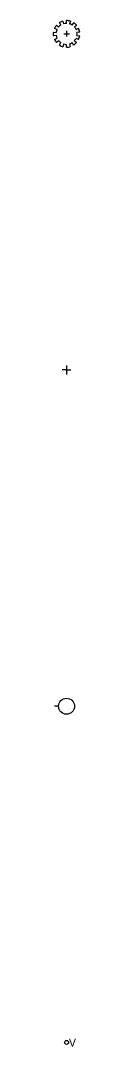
# Model space of a CAD drawing. Extents: x 98 to 2902, y -6 to 903.
# Drawn here: x 898 to 902, y 749.4 to 902 of the extents above; entities that cross this region are included whole.
import ezdxf

# ---------------------------------------------------------------- set-up
doc = ezdxf.new("R2010")
doc.units = 0
for name, color, linetype in [('V-FUEL-DEVC', 7, 'Continuous'), ('V-SITE-OTLN', 7, 'Continuous'), ('V-SITE-VEGE', 7, 'Continuous'), ('V-WATR-DEVC', 7, 'Continuous')]:
    doc.layers.add(name, color=color, linetype=linetype)

msp = doc.modelspace()

# ---------------------------------------------------------------- linework, layer by layer
at = {"layer": 'V-FUEL-DEVC'}
msp.add_circle((900, 750), 0.298, dxfattribs=at)
at = {"layer": 'V-SITE-OTLN'}
for p, q in [((900, 850), (899.35, 850)), ((900, 850.65), (900, 849.35)), ((900, 850), (900.65, 850))]:
    msp.add_line(p, q, dxfattribs=at)
at = {"layer": 'V-SITE-VEGE'}
for p, q in [((899.17, 901.3), (898.93, 901.65)), ((899.46, 901.89), (899.56, 901.47)), ((900, 901.53), (900.01, 901.96)), ((900.57, 901.88), (900.45, 901.47)), ((900.84, 901.29), (901.08, 901.64)), ((898.03, 900.25), (898.46, 900.18)), ((898.58, 900.61), (898.19, 900.78)), ((898.49, 901.26), (898.81, 900.98)), ((900, 900.42), (900, 899.58)), ((901.51, 901.27), (901.19, 900.99)), ((901.42, 900.62), (901.8, 900.82)), ((901.97, 900.25), (901.54, 900.19)), ((898.46, 899.76), (898.04, 899.69)), ((898.19, 899.16), (898.58, 899.35)), ((898.83, 898.96), (898.5, 898.68)), ((898.94, 898.3), (899.15, 898.68)), ((899.58, 900), (900.42, 900)), ((901.08, 898.31), (900.85, 898.68)), ((901.17, 898.95), (901.5, 898.68)), ((901.81, 899.15), (901.41, 899.31)), ((901.54, 899.75), (901.97, 899.7)), ((899.58, 898.48), (899.46, 898.07)), ((900, 897.99), (900, 898.42)), ((900.43, 898.49), (900.56, 898.08))]:
    msp.add_line(p, q, dxfattribs=at)
for radius, start, end in [(1.98, 105.972, 122.5562), (1.98, 73.2952, 89.5718), (1.98, 40.7122, 57.1166), (1.98, 172.27, 188.583), (1.98, 139.7777, 156.0738), (1.56, 156.0557, 172.7558), (1.56, 122.254, 140.086), (1.56, 89.9461, 106.3473), (1.56, 57.451, 73.0843), (1.56, 24.4529, 40.4774), (1.56, 351.5431, 7.6203), (1.98, 7.9671, 24.8625), (1.98, 204.5394, 220.9852), (1.56, 188.0619, 204.0332), (1.56, 221.2062, 236.7795), (1.56, 285.9559, 303.0564), (1.98, 302.8434, 319.0222), (1.56, 318.6432, 334.5795), (1.98, 335.3123, 351.7042), (1.98, 237.6108, 254.1981), (1.56, 254.31, 270.043), (1.98, 270.0356, 286.342)]:
    msp.add_arc((900, 899.98), radius, start, end, dxfattribs=at)
at = {"layer": 'V-WATR-DEVC'}
msp.add_line((898.81, 800), (898.21, 800), dxfattribs=at)
msp.add_circle((900, 800), 1.19, dxfattribs=at)

# ---------------------------------------------------------------- texts
at = {"layer": 'V-FUEL-DEVC'}
msp.add_text('V', height=1.19, dxfattribs=at).set_placement((900.35, 749.4))

doc.saveas('drawing.dxf')
